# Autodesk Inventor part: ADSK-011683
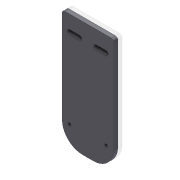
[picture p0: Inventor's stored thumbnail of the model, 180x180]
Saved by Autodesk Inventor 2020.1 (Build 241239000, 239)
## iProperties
Created: 2000-02
Part Number: ADSK-011683
Material: Pearson HRS
Description: PLT-22,FH,CP,03,050,115,NNDD,MNT,ADJUST
Document SubType Name: Modeling
Designer: sspink
Density: 7.83 g/cm^3
Appearance: Métal - Acier
Mass: 2781.31 g
Surface Area: 810.247 cm^2
Volume: 355.212 cm^3
Control State: 0
Master: False
Checked Out: False
Shininess: 0.0
Length Units: 11269
Angle Units: 11279
Time Units: 11290
Mass Units: 11283
Length Display Precision: 3
Angle Display Precision: 2
Compacted: True
Cutlength: 11.5
Material Desc: FLAT,HRS,0.38 X 5.00
Material_Number: A084412
Dimensions: 127x294x10 mm
Mass: 2,781 kg
DocNumber: ADSK-011683.ipt
Folder: 01 - Themengebiete\Simplification\01 - Packaging machine\
VDS_Category: 3D Komponenten
Density: 0.0
Volumn: 0.0
Area: 0.0
PropertySet Name: Model Information
Author: sspink
Revision Number: -
Title: fixing plate
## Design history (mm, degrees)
node "Solide1"
  node "Extrusion1" dims "d2" = 10, "d3" = 0
  node "Fillet1" dims "d11" = 50
  node "Extrusion2" dims "d17" = 9.525, "d18" = 0
  node "Fillet2" dims "d19" = 6.35
  node "Hole3" dims "d32" = 6.647, "d33" = 9.525, "d34" = 6.35, "d35" = 60 deg, "d36" = 19.05, "d37" = 118 deg, "d39" = 16
sketch "Sketch1"
  geometry: L1 (-63.5, -147)-(63.5, -147); L2 (63.5, -147)-(63.5, 147); L3 (63.5, 147)-(-63.5, 147); L4 (-63.5, 147)-(-63.5, -147); 3 further points
  constraints: 8 end point, 2 midpoint, 2 parallel, 1 horizontal, 1 horizontal alignment, 1 perpendicular, 1 vertical alignment
  dimensions: "d0" = 127 distance between parallel lines of L2 L4; "d1" = 294 distance between parallel lines of L1 L3
workplane "Arbeitsebene1"
workpoint "Arbeitspunkt1"
workpoint "Arbeitspunkt2"
workaxis "Arbeitsachse1"
workaxis "Arbeitsachse2"
sketch "Sketch3"
  geometry: L1 (-63.5, 147)-(63.5, 147) reference; L2 (-45, 114)-(-20, 114); L3 (-20, 114)-(-20, 104); L4 (-20, 104)-(-45, 104); L5 (-45, 104)-(-45, 114); L6 (20, 114)-(45, 114); L7 (45, 114)-(45, 104); L8 (45, 104)-(20, 104); L9 (20, 104)-(20, 114); L10 (-45, 109)-(-20, 109); L11 (20, 109)-(45, 109); L12 (-32.5, 109)-(32.5, 109); A1 r 5 centre (-45, 109) between (-45, 114) and (-45, 104); A2 r 5 centre (-20, 109) between (-20, 104) and (-20, 114); A3 r 5 centre (20, 109) between (20, 114) and (20, 104); A4 r 5 centre (45, 109) between (45, 104) and (45, 114); 2 further points
  constraints: 22 end point, 8 point on circle, 4 centre point, 4 horizontal, 4 midpoint, 4 parallel, 4 tangent, 2 perpendicular, 1 collinear, 1 equal radius, 1 horizontal alignment, 1 vertical alignment
  dimensions: "d12" = 25 distance between parallel lines of L3 L5; "d13" = 10 distance between parallel lines of L4 L2; "d15" = 38 distance from line of L10.start L1; "d38" = 65 distance of L12.start L12.end
sketch "Sketch5"
  geometry: L1 (-57.15, 147)-(57.15, 147) reference; L2 (13.5, -147)-(-13.5, -147) reference; L3 (0, 147)-(0, -147); L4 (45, -98)-(-45, -98); C1 r 4.779 at (-45, -98); C2 r 4.779 at (45, -98); 1 further point
  constraints: 4 end point, 3 midpoint, 2 centre point, 2 coincident, 1 point on line
  dimensions: "d40" = 90 distance of L4.start L4.end; "d41" = 49 distance between parallel lines of L2 L4
node "Corps solides"
node "Corps surfaciques"
